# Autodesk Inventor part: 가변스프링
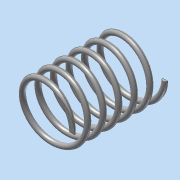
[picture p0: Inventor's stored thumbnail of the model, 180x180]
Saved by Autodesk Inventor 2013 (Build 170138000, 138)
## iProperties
Created: 2018-06
Part Number: 가변스프링
Material: 강철, 연강
Document SubType Name: Modeling
Designer: Administrator
Mass: 82.807 g
Surface Area: 106.473 cm^2
Volume: 10.5352 cm^3
Density: 7.86 g/cm^3
Author: Administrator
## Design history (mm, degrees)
sketch "스케치1"
  geometry: L1 (0, 0)-(0, 73.25); L2 (0, 0)-(22.5, 0); L3 (0, 73.25)-(22.5, 73.25); C1 r 2 at (22.5, 0)
  constraints: 6 end point, 1 centre point, 1 parallel, 1 perpendicular, 1 vertical
  dimensions: "d0" = 4 diameter of C1; "d1" = 73.25 distance of L1.start L1.end (derived); "d2" = 22.5 distance of L1.start L2.end; "d3" = 45 diameter of L3.end L1
feature "코일1" sketch "스케치1" pitch "d4" = 10; turns "d6" = 6; dims "d5" = 73.25 (= d1), "d7" = 0, angle "d8" = 90 deg, angle "d9" = 90 deg, "d10" = 0, "d11" = 0
sketch "스케치2"
  geometry: L1 (73.25, 27.5)-(0, 27.5); L2 (0, 27.5)-(0, -27.5); L3 (0, -27.5)-(73.25, -27.5); L4 (73.25, -27.5)-(73.25, 27.5); 2 further points
  constraints: 8 end point, 2 parallel, 1 coincident, 1 horizontal, 1 midpoint, 1 perpendicular
  dimensions: "d12" = 73.25 distance of L1.start L1.end (derived); "d14" = 55 distance of L3.end L1.start
extrude "돌출1" sketch "스케치2" stored distance "d15" = 60; taper "d16" = 0 deg
node "솔리드1"
